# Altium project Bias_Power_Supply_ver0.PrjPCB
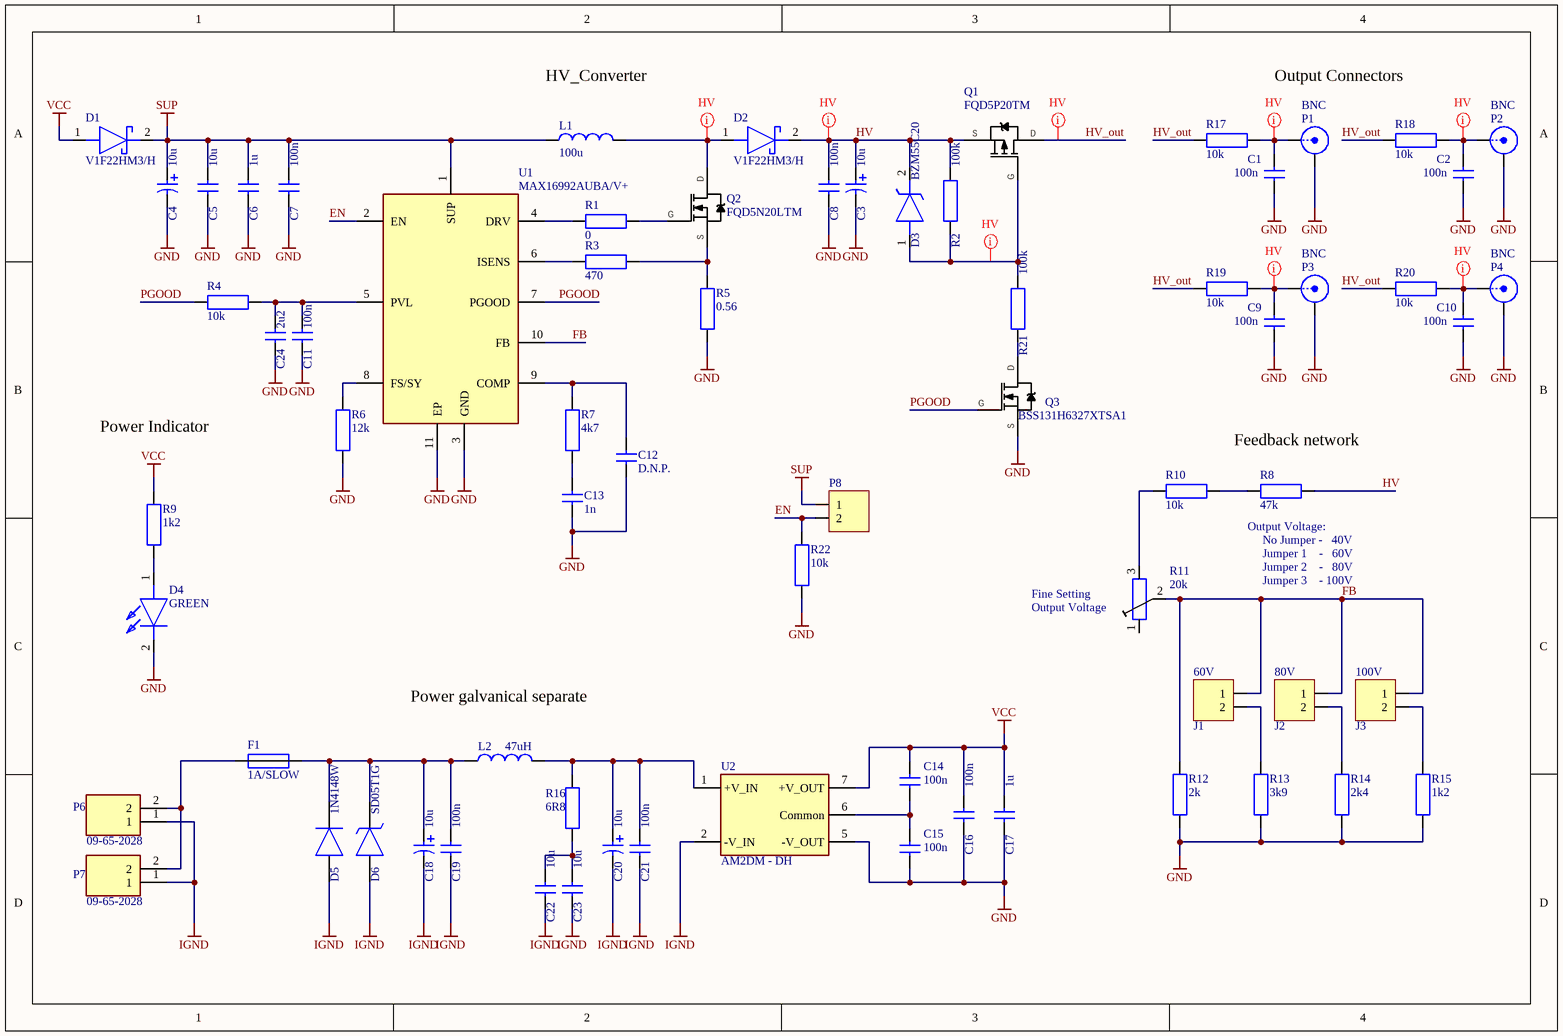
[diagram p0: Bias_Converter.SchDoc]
1 sheet, 70 parts. Net scope: global (net labels, ports and power ports of the same name join across sheets).
Board file: Bias_Power_Supply.PcbDoc

## Sheet Bias_Converter.SchDoc
size A4

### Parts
C1  100n  [SMD_CAPACITOR_1206]
C2  100n  [SMD_CAPACITOR_1206]
C3  10u  [CAPPR3.5-8x11.5]
C4  10u  [SMD_CAP_POL_D5.0mm]
C5  10u  [SMD_CAPACITOR_1206]
C6  1u  [SMD_CAPACITOR_0603]
C7  100n  [SMD_CAPACITOR_0603]
C8  100n  [SMD_CAPACITOR_1206]
C9  100n  [SMD_CAPACITOR_1206]
C10  100n  [SMD_CAPACITOR_1206]
C11  100n  [SMD_CAPACITOR_0603]
C12  D.N.P.  [SMD_CAPACITOR_0603]
C13  1n  [SMD_CAPACITOR_0603]
C14  100n  [SMD_CAPACITOR_0603]
C15  100n  [SMD_CAPACITOR_0603]
C16  100n  [SMD_CAPACITOR_0603]
C17  1u  [SMD_CAPACITOR_0603]
C18  10u  [SMD_CAP_POL_D5.0mm]
C19  100n  [SMD_CAPACITOR_0603]
C20  10u  [SMD_CAP_POL_D5.0mm]
C21  100n  [SMD_CAPACITOR_0603]
C22  10u  [SMD_CAPACITOR_1206]
C23  10u  [SMD_CAPACITOR_1206]
C24  2u2  [SMD_CAPACITOR_0603]
D1  V1F22HM3/H  [SMD_DO-219]
D2  V1F22HM3/H  [SMD_DO-219]
D3  BZM55C20  [SMD_DIO-MINIMELF]
D4  GREEN  [SMD_LED_0603]
D5  1N4148W  [SMD_SOD-123]
D6  SD05T1G  [SMD_SOD-323]
F1  1A/SLOW  [SMD_RESISTOR_1206]
J1  Header_2pin_1row  [61300211121]  (value not drawn)
J2  Header_2pin_1row  [61300211121]  (value not drawn)
J3  Header_2pin_1row  [61300211121]  (value not drawn)
L1  100u  [SMD_INDUCTOR_7.3MM]
L2  47uH  [SMD_INDUCTOR_7.3MM]
P1  BNC  [BNC_0315637]
P2  BNC  [BNC_0315637]
P3  BNC  [BNC_0315637]
P4  BNC  [BNC_0315637]
P6  09-65-2028  [SHDR2W165P0X396_1X2_716X1062X1425P]
P7  09-65-2028  [SHDR2W165P0X396_1X2_716X1062X1425P]
P8  Header_2pin_1row  [61300211121]  (value not drawn)
Q1  FQD5P20TM  [SMD_DPAK]
Q2  FQD5N20LTM  [SMD_DPAK]
Q3  BSS131H6327XTSA1  [SMD_SOT-23]
R1  0  [SMD_RES_0603]
R2  100k  [SMD_RESISTOR_1206]
R3  470  [SMD_RES_0603]
R4  10k  [SMD_RES_0603]
R5  0.56  [SMD_RESISTOR_1206]
R6  12k  [SMD_RES_0603]
R7  4k7  [SMD_RES_0603]
R8  47k  [SMD_RESISTOR_1206]
R9  1k2  [SMD_RESISTOR_0805]
R10  10k  [SMD_RESISTOR_1206]
R11  20k  [THT_TRIM_3296Y1502LF]
R12  2k  [SMD_RES_0603]
R13  3k9  [SMD_RES_0603]
R14  2k4  [SMD_RES_0603]
R15  1k2  [SMD_RES_0603]
R16  6R8  [SMD_RESISTOR_1206]
R17  10k  [SMD_RESISTOR_1206]
R18  10k  [SMD_RESISTOR_1206]
R19  10k  [SMD_RESISTOR_1206]
R20  10k  [SMD_RESISTOR_1206]
R21  100k  [SMD_RESISTOR_1206]
R22  10k  [SMD_RES_0603]
U1  MAX16992AUBA/V+  [SOP50P490X110-11N]
U2  AM2DM - DH  [AM2DM_dual_3]

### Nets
GND: C1.1 C2.1 C3.2 C4.2 C5.1 C6.1 C7.1 C8.1 C9.1 C10.1 C11.1 C12.1 C13.1 C15.1 C16.1 C17.1 C24.1 D4.2(K) P1.1(Y) P2.1(Y) P3.1(Y) P4.1(Y) Q3.S R5.1 R6.1 R12.1 R13.1 R14.1 R15.1 R22.2 U1.3(GND) U1.11(EP) U2.5(-V_OUT)
IGND: C18.2 C19.1 C20.2 C21.1 C22.1 C23.1 D5.1(A) D6.1(A) P6.1 P7.1 U2.2(-V_IN)
SUP: C4.1 C5.2 C6.2 C7.2 D1.2(K) L1.1 P8.1 U1.1(SUP)
VCC: C14.2 C16.2 C17.2 D1.1(A) R9.1 U2.7(+V_OUT)
EN: P8.2 R22.1 U1.2(EN)
FB: J1.1 J2.1 J3.1 R11.2(WIPER) R12.2 U1.10(FB)
HV: C3.1 C8.2 D2.2(K) D3.2(K) Q1.S R2.2 R8.1
HV_out: Q1.D R17.2 R18.2 R19.2 R20.2
PGOOD: Q3.G R4.2 U1.7(PGOOD)
NetC1_2: C1.2 P1.2(X) R17.1
NetC2_2: C2.2 P2.2(X) R18.1
NetC9_2: C9.2 P3.2(X) R19.1
NetC10_2: C10.2 P4.2(X) R20.1
NetC11_2: C11.2 C24.2 R4.1 U1.5(PVL)
NetC12_2: C12.2 R7.2 U1.9(COMP)
NetC13_2: C13.2 R7.1
NetC14_1: C14.1 C15.2 U2.6(Common)
NetC18_1: C18.1 C19.2 D5.2(K) D6.2(K) F1.2 L2.1
NetC20_1: C20.1 C21.2 L2.2 R16.2 U2.1(+V_IN)
NetC22_2: C22.2 C23.2 R16.1
NetD2_1: D2.1(A) L1.2 Q2.D
NetD3_1: D3.1(A) Q1.G R2.1 R21.2
NetD4_1: D4.1(A) R9.2
NetF1_1: F1.1 P6.2 P7.2
NetJ1_2: J1.2 R13.2
NetJ2_2: J2.2 R14.2
NetJ3_2: J3.2 R15.2
NetQ2_G: Q2.G R1.2
NetQ2_S: Q2.S R3.2 R5.2
NetQ3_D: Q3.D R21.1
NetR1_1: R1.1 U1.4(DRV)
NetR3_1: R3.1 U1.6(ISENS)
NetR6_2: R6.2 U1.8(FS/SY)
NetR8_2: R8.2 R10.1
NetR10_2: R10.2 R11.3(CW)

Not connected (* = marked no-connect by the designer): R11 1(CCW)

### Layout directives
net class HV: HV, HV_out, NetC1_2, NetC2_2, NetC9_2, NetC10_2, NetD2_1, NetD3_1

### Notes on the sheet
- HV_Converter
- Output Connectors
- Power Indicator
- Feedback network
- (near R8) Output Voltage:
  No Jumper -   40V
  Jumper 1    -   60V
  Jumper 2    -   80V
  Jumper 3    - 100V
- (near R11) Fine Setting Output Voltage
- Power galvanical separate
- (near J1) 60V
- 80V
- (near J3) 100V

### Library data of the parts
C1 C2 C5-C17 C19 C21-C24 = Capacitor
C3 C4 C18 C20 = Capacitor_pol
D1 D2 = Schottky_Diode
D3 = Zener_Diode: pin to pad: 1>A 2>C
D4 = LED
D5 = Diode
D6 = TVS_Diode_unidirect
F1 = Fuse
J1-J3 P8 = Header_2pin_1row: Manufacturer: Wurth Electronics
L1 L2 = Inductor
P6 P7 = 09-65-2028: Connector; Manufacturer_Name: Molex; Allied_Number: 70374002
Q1 = Transistor_P-mosfet: pin to pad: D>4 G>1 S>3
Q2 = Transistor_N-Mosfet: pin to pad: D>4 G>1 S>3
Q3 = Transistor_N-Mosfet: pin to pad: D>3 G>1 S>2
R1-R10 R12-R22 = Resistor
R11 = Resistor_trim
